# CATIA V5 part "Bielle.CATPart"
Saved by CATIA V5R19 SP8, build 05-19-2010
Part number: Bielle100
Bounding box of the stored display mesh (mm): x -30 to 30, y -25 to 25, z -30 to 620
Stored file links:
  C:\Users\ThinkMotion\Desktop\EU_thinkMotion\iao\IAO_MMS_Groupe3\yschmidt\Train1434_yschmidt\Train1434_yschmidt\Bielle.CATPart
  C:\Users\ThinkMotion\Desktop\EU_thinkMotion\iao\IAO_MMS_Groupe3\yschmidt\Train1434_yschmidt\Train1434_yschmidt\AssemblageTrainOptimise.CATProduct
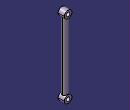
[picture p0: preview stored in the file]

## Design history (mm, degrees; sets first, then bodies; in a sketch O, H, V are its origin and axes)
Set1
  Plane1: linked copy from another document
  Line1: linked copy from another document
  Line2: linked copy from another document
Body1 (main body)
  Sketch1 on xy-plane, origin (0, 0, 0), H (1, 0, 0), V (0, 1, 0)
    circle A1 centre (0, 0) radius 20
    radius A1 = 20
  Pad1: profile Sketch1, direction (0, 0, 1), up to Plane1
  Sketch2 on zx-plane, origin (0, 0, 0), H (-1, 0, 0), V (0, 0, 1)
    circle A1 centre (0, 0) radius 30
    circle A2 centre (0, 590) radius 30
    reference projected point E1 (0, 590) from Line1
    reference projected point E2 (0, 0) from Line2
    radius A2 = 30
    radius A1 = 30
    concentricity: E1 A2, E2 A1
  Pad2: profile Sketch2, direction (0, 1, 0), length 25
  Pad3: profile Sketch2, direction (0, -1, 0), length 25
  Sketch3 on end face of Pad3, origin (-0.1241, -25, 202.3561), H (1, 0, 0), V (0, 0, 1)
    point P1 (0.1241, 387.6439)
    reference projected point E1 (0.1241, 387.6439) from Line1
    coincidence: P1 E1
  Hole1: placed by Sketch3, at (0, -25, 590) direction (0, 1, 0), diameter 30, through (limit type 6)
  Sketch4 on end face of Pad3, origin (-5.7577, -25, 1.4638), H (1, 0, 0), V (0, 0, 1)
    point P1 (5.7577, -1.4638)
    reference projected point E1 (5.7577, -1.4638) from Line2
    coincidence: P1 E1
  Hole2: placed by Sketch4, at (0, -25, 0) direction (0, 1, 0), diameter 30, through (limit type 6)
